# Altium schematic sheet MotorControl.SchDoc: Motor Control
size A4; DocumentNumber: MB1167; Revision: B.1; SheetNumber: 13; SheetTotal: 17; Project: STM327x6G-EVAL
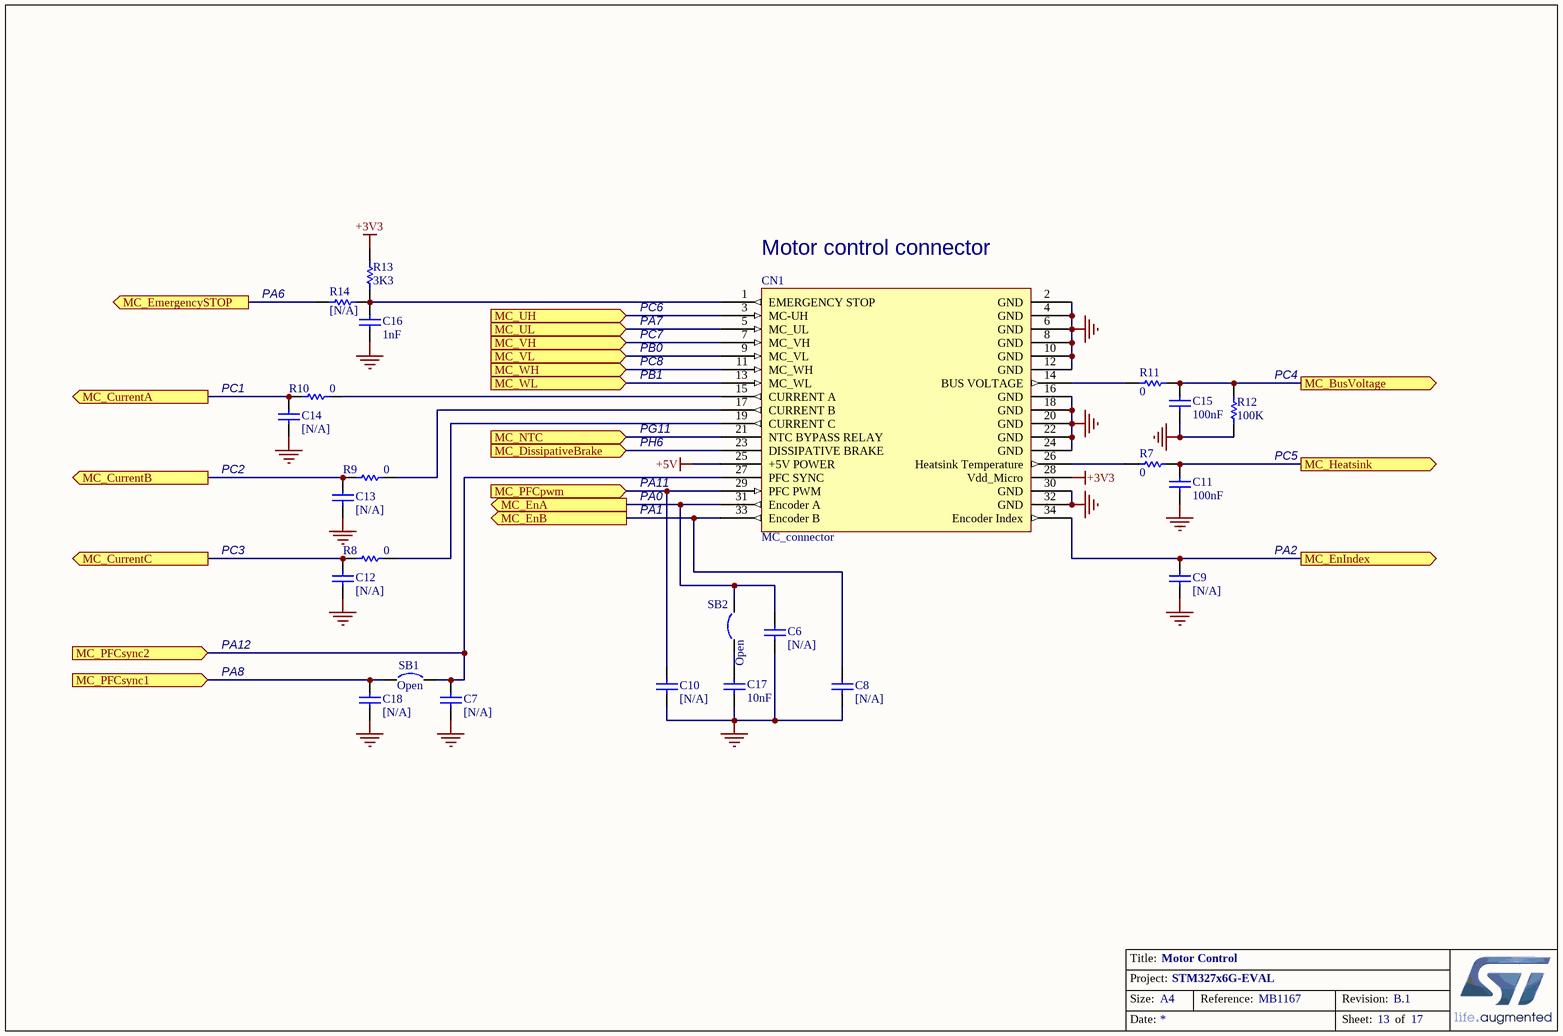
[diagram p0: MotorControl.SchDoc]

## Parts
C6  [N/A]  [0603C]
C7  [N/A]  [0603C]
C8  [N/A]  [0603C]
C9  [N/A]  [0603C]
C10  [N/A]  [0603C]
C11  100nF  [0603C]
C12  [N/A]  [0603C]
C13  [N/A]  [0603C]
C14  [N/A]  [0603C]
C15  100nF  [0603C]
C16  1nF  [0603C]
C17  10nF  [0603C]
C18  [N/A]  [0603C]
CN1  MC_connector  [IDC34S]
R7  0  [0603R]
R8  0  [0603R]
R9  0  [0603R]
R10  0  [0603R]
R11  0  [0603R]
R12  100K  [0603R]
R13  3K3  [0603R]
R14  [N/A]  [0603R]
SB1  Open  [SB_0603]
SB2  Open  [SB_0603]

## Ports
MC_BusVoltage (out), MC_CurrentA (out), MC_CurrentB (out), MC_CurrentC (out), MC_DissipativeBrake (in), MC_EmergencySTOP (out), MC_EnA (out), MC_EnB (out), MC_EnIndex (out), MC_Heatsink (out), MC_NTC (in), MC_PFCpwm (in), MC_PFCsync1 (in), MC_PFCsync2 (in), MC_UH (in), MC_UL (in), MC_VH (in), MC_VL (in), MC_WH (in), MC_WL (in)

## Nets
+3V3: CN1.28(Vdd_Micro) R13.2
+5V: CN1.25(+5V_POWER)
GND: C6.1 C7.1 C8.1 C9.1 C10.1 C11.2 C12.1 C13.1 C14.1 C15.2 C16.1 C17.2 C18.1 CN1.2(GND) CN1.4(GND) CN1.6(GND) CN1.8(GND) CN1.10(GND) CN1.12(GND) CN1.16(GND) CN1.18(GND) CN1.20(GND) CN1.22(GND) CN1.24(GND) CN1.30(GND) CN1.32(GND) R12.2
MC_BusVoltage: C15.1 R11.2 R12.1 ; port MC_BusVoltage
MC_CurrentA: C14.2 R10.1 ; port MC_CurrentA
MC_CurrentB: C13.2 R9.1 ; port MC_CurrentB
MC_CurrentC: C12.2 R8.1 ; port MC_CurrentC
MC_DissipativeBrake: CN1.23(DISSIPATIVE_BRAKE) ; port MC_DissipativeBrake
MC_EmergencySTOP: R14.2 ; port MC_EmergencySTOP
MC_EnA: C6.2 CN1.31(Encoder_A) SB2.2 ; port MC_EnA
MC_EnB: C8.2 CN1.33(Encoder_B) ; port MC_EnB
MC_EnIndex: C9.2 CN1.34(Encoder_Index) ; port MC_EnIndex
MC_Heatsink: C11.1 R7.2 ; port MC_Heatsink
MC_NTC: CN1.21(NTC_BYPASS_RELAY) ; port MC_NTC
MC_PFCpwm: C10.2 CN1.29(PFC_PWM) ; port MC_PFCpwm
MC_PFCsync1: C18.2 SB1.1 ; port MC_PFCsync1
MC_PFCsync2: C7.2 CN1.27(PFC_SYNC) SB1.2 ; port MC_PFCsync2
MC_UH: CN1.3(MC-UH) ; port MC_UH
MC_UL: CN1.5(MC_UL) ; port MC_UL
MC_VH: CN1.7(MC_VH) ; port MC_VH
MC_VL: CN1.9(MC_VL) ; port MC_VL
MC_WH: CN1.11(MC_WH) ; port MC_WH
MC_WL: CN1.13(MC_WL) ; port MC_WL
NetC16_2: C16.2 CN1.1(EMERGENCY_STOP) R13.1 R14.1
NetC17_1: C17.1 SB2.1
NetCN1_14: CN1.14(BUS_VOLTAGE) R11.1
NetCN1_15: CN1.15(CURRENT_A) R10.2
NetCN1_17: CN1.17(CURRENT_B) R9.2
NetCN1_19: CN1.19(CURRENT_C) R8.2
NetCN1_26: CN1.26(Heatsink_Temperature) R7.1

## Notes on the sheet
- (near R14) PA6
- PC6
- (near CN1) Motor control connector
- PA7
- PB0
- PB1
- PC7
- PC8
- (near R12) PC4
- PC1
- PG11
- PH6
- PC2
- PA1
- PA0
- PA11
- (near R12) PC5
- PC3
- PA2
- PA12
- PA8

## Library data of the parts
C6-C10 C12-C14 C18 = cap: Capacitor; Value: 100pF
C11 C15 = Cap: Capacitor; Value: 10nF
C16 C17 = CAP: Capacitor; Value: 100pF
R7-R11 R13 R14 = Res1: Resistor; Value: 1K
R12 = res1: Resistor; Value: 1K
SB1 SB2 = Circuit Breaker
